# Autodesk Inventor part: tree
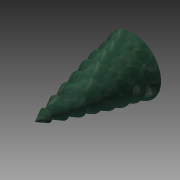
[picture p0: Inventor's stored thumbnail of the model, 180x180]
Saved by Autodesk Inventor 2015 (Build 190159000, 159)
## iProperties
Created: 2012-11
Part Number: tree
Material: Generic
Document SubType Name: Modeling
Designer: ronnieharmon
Density: 1 g/cm^3
Appearance: Default
Author: ronnieharmon
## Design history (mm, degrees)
sketch "Sketch1"
  geometry: L1 (0, 0)-(1.866, -3.529); L2 (1.866, -3.529)-(0.933, -3.529); L3 (0.933, -3.529)-(3.137, -7.697); L4 (3.137, -7.697)-(2.035, -7.697); L5 (2.035, -7.697)-(4.304, -11.988); L6 (4.304, -11.988)-(3.17, -11.988); L7 (3.17, -11.988)-(5.271, -15.962); L8 (5.271, -15.962)-(4.221, -15.962); L9 (4.221, -15.962)-(6.326, -19.943); L10 (6.326, -19.943)-(5.273, -19.943); L11 (5.273, -19.943)-(7.141, -23.475); L12 (7.141, -23.475)-(5.799, -23.475); L13 (5.799, -23.475)-(7.714, -27.096); L14 (7.714, -27.096)-(6.757, -27.096); L15 (6.757, -27.096)-(8.707, -30.784); L16 (8.707, -30.784)-(2.035, -30.784); L17 (2.035, -30.784)-(2.035, -34.59); L18 (2.035, -34.59)-(0, -34.59); L19 (0, -34.59)-(0, 0)
  constraints: 38 end point, 14 parallel, 3 perpendicular, 1 horizontal
revolve "Revolution1" sketch "Sketch1" stored, may be unused: angle "d0" = 90 deg
body "Solid1"
